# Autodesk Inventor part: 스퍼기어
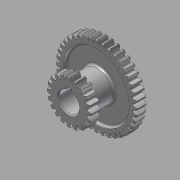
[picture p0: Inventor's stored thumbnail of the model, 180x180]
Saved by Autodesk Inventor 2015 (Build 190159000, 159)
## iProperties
Created: 2015-09
Part Number: 스퍼기어
Material: 강철, 연강
Document SubType Name: Modeling
Designer: mduedu
Density: 1 g/cm^3
Appearance: 강철
Author: mduedu
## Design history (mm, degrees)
sketch "스케치1"
  geometry: C1 r 38 at (0, 0); C2 r 40 at (0, 0); C3 r 35.5 at (0, 0); 1 further point
  constraints: 3 centre point, 3 coincident
  dimensions: "d0" = 76 diameter of C1; "d2" = 2 radial gap between concentric circles of C2 C1; "d3" = 71 diameter of C3 (computed from d0)
extrude "돌출1" new body sketch "스케치1" stored distance "d4" = 10; taper "d5" = 0 deg
sketch "스케치2"
  geometry: L1 (0, 35.5)-(0, -35.5); L2 (0, 0)-(40, 0); L3 (0, 0.57)-(39.996, 0.57); L4 (0, 1.57)-(39.969, 1.57); L5 (0, 2.07)-(39.946, 2.07); A1 r 35.5 centre (0, 0) between (0, 35.5) and (0, -35.5) reference; A2 r 40 centre (0, 0) between (40, 0) and (39.946, 2.07) reference; A3 r 9.234 centre (34.93, -7.149) between (39.996, 0.57) and (35.44, 2.07); A4 r 9.234 centre (34.93, 7.149) between (35.44, -2.07) and (39.996, -0.57); A5 r 40 centre (0, 0) between (39.996, -0.57) and (39.996, 0.57); A6 r 35.5 centre (0, 0) between (35.44, -2.07) and (35.44, 2.07); 4 further points
  constraints: 16 point on circle, 10 end point, 6 point on line, 4 centre point, 3 coincident, 3 parallel, 3 symmetric about line, 2 midpoint, 1 perpendicular, 1 vertical, 3 other
  dimensions: "d6" = 0.5 distance between parallel lines of L4 L5; "d8" = 1 distance between parallel lines of L3 L4; "d9" = 1.57 distance between parallel lines of L2 L4
extrude "돌출2" join sketch "스케치2" distance "d10" = 5; taper "d12" = 0 deg; dims "d11" = 5, "d13" = 0
fillet "모깎기1" dims "d17" = 0.5
chamfer "모따기1" distance "d21" = 1; stored, may be unused: second distance "d22" = 2, angle "d23" = 45 deg
sketch "스케치3"
  geometry: C1 r 32.5 at (0, 0); C2 r 15 at (0, 0); 1 further point
  constraints: 2 centre point, 2 coincident
  dimensions: "d27" = 65 diameter of C1; "d28" = 30 diameter of C2
extrude "돌출3" cut sketch "스케치3" distance "d29" = 3; taper "d30" = 0 deg
fillet "모깎기2" dims "d31" = 2
node "작업 평면2"
  node "작업 평면1"
sketch "스케치4"
  geometry: C1 r 15 at (0, 0) reference; 1 further point
extrude "돌출4" join sketch "스케치4" stored distance "d34" = 3; taper "d35" = 0 deg
sketch "스케치5"
  geometry: C1 r 17.5 at (0, 0); C2 r 20 at (0, 0); C3 r 22 at (0, 0); 1 further point
  constraints: 3 centre point, 3 coincident
  dimensions: "d36" = 40 diameter of C2; "d38" = 2 radial gap between concentric circles of C2 C3; "d39" = 35 diameter of C1 (= d36 - 2.5 x d38)
extrude "돌출6" join sketch "스케치5" distance "d46" = 10; taper "d47" = 0 deg
sketch "스케치6"
  geometry: L1 (0, 0)-(0, 22); L2 (-17.5, 0)-(17.5, 0); L3 (-0.57, 0)-(-0.57, 21.993); L4 (-1.57, 0)-(-1.57, 21.944); L5 (-2.07, 0)-(-2.07, 21.902); A1 r 22 centre (0, 0) between (0, 22) and (-0.57, 21.993) reference; A2 r 17.5 centre (0, 0) between (-17.5, 0) and (17.5, 0) reference; A3 r 9.431 centre (7.348, 16.868) between (-0.57, 21.993) and (-2.07, 17.377); A4 r 9.431 centre (-7.348, 16.868) between (2.07, 17.377) and (0.57, 21.993); A5 r 17.5 centre (0, 0) between (2.07, 17.377) and (-2.07, 17.377); A6 r 22 centre (0, 0) between (0.57, 21.993) and (-0.57, 21.993); 4 further points
  constraints: 16 point on circle, 10 end point, 5 point on line, 4 centre point, 3 coincident, 3 symmetric about line, 2 parallel, 2 perpendicular, 1 midpoint, 1 vertical, 3 other
  dimensions: "d40" = 0.5 distance between parallel lines of L4 L5; "d42" = 1 distance between parallel lines of L3 L4; "d43" = 1.57 distance between parallel lines of L1 L4
extrude "돌출5" join sketch "스케치6" distance "d44" = 10; taper "d45" = 0 deg
fillet "모깎기3" dims "d48" = 0.5
chamfer "모따기2" distance "d49" = 1; stored, may be unused: second distance "d50" = 2, angle "d51" = 45 deg
sketch "스케치7"
  geometry: C1 r 10 at (0, 0); 1 further point
  constraints: 1 centre point, 1 coincident
  dimensions: "d55" = 20 diameter of C1
extrude "돌출7" cut sketch "스케치7" stored distance "d56" = 10; taper "d57" = 0 deg
sketch "스케치8"
  geometry: L1 (-9.539, -3)-(-12.8, -3); L2 (-12.8, -3)-(-12.8, 3); L3 (-12.8, 3)-(-9.539, 3); L4 (-9.539, 3)-(-9.539, -3); A1 r 10 centre (0, 0) between (-9.539, -3) and (-9.539, 3) reference; 2 further points
  constraints: 8 end point, 3 point on circle, 2 parallel, 1 horizontal, 1 horizontal alignment, 1 perpendicular
  dimensions: "d58" = 6 distance of L1.end L2.end; "d60" = 22.8 distance from line of point (10, 0) L2
extrude "돌출8" cut sketch "스케치8" stored distance "d61" = 10; taper "d62" = 0 deg
chamfer "모따기3" distance "d63" = 1; stored, may be unused: second distance "d64" = 2, angle "d65" = 45 deg
fillet "모깎기4" dims "d66" = 2
node "솔리드1"
pattern_circular "원형 패턴3" dims "d25" = 360 deg
mirror "대칭1"
pattern_circular "원형 패턴4" dims "d53" = 360 deg
other parameters: "d32" = 5, "d33" = 42
